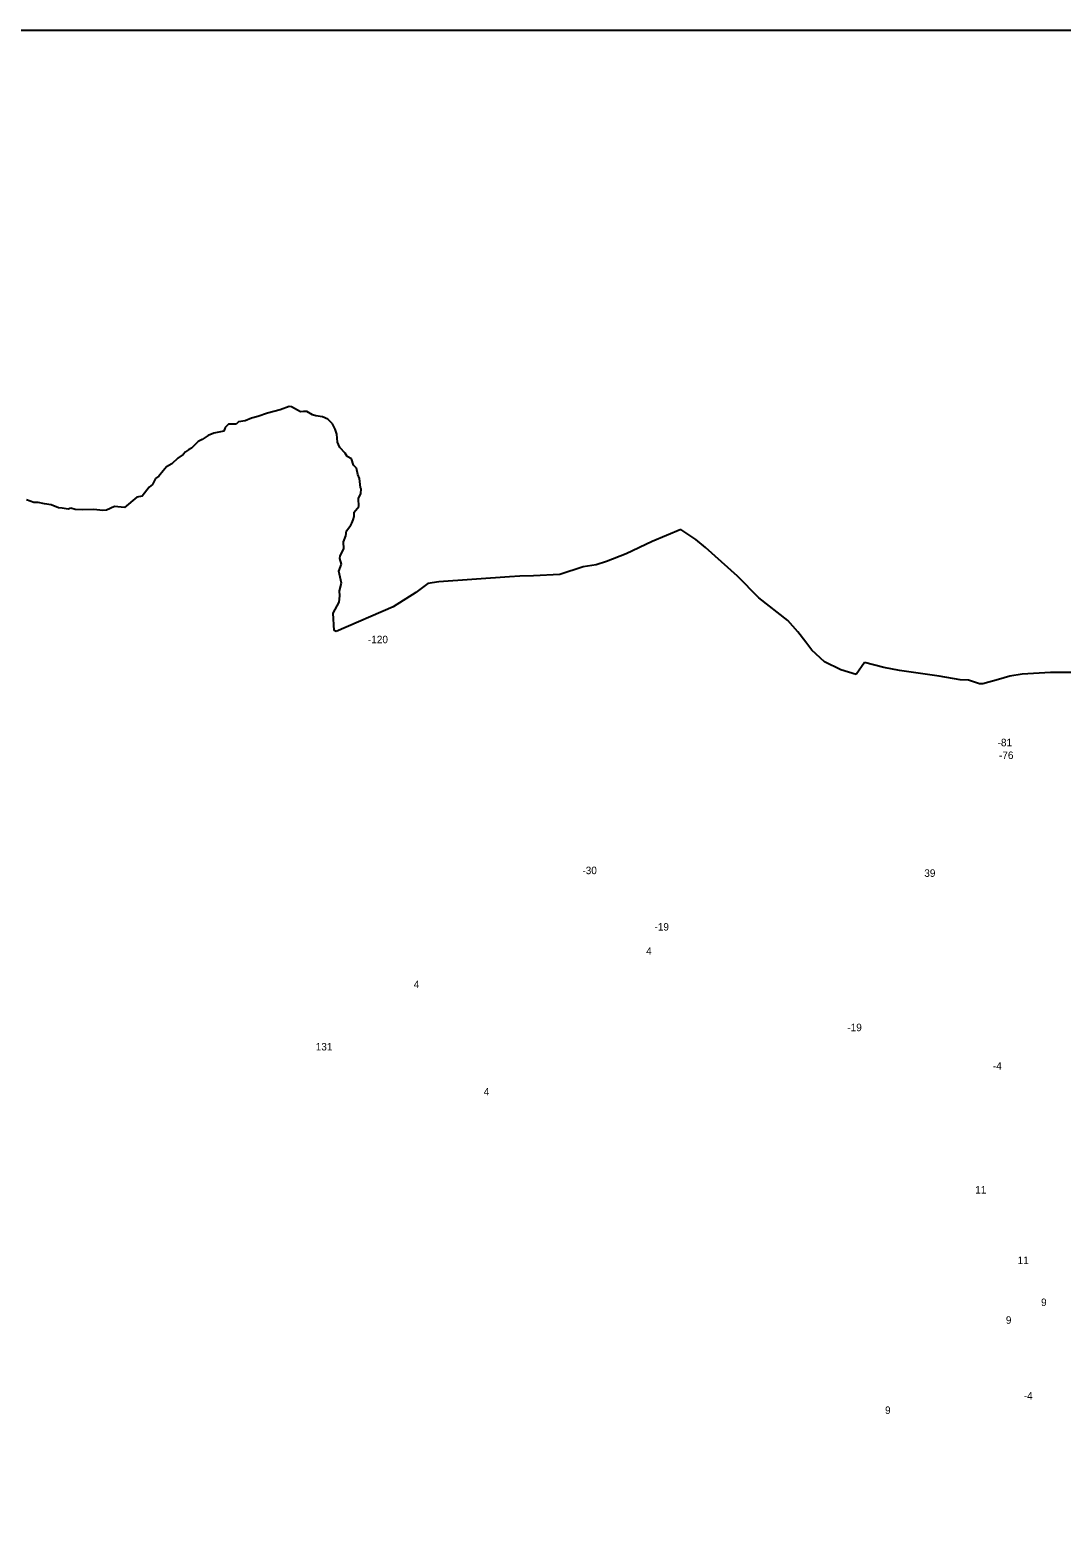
# Model space of a CAD drawing. Extents: x -780246 to -774760, y -968897 to -964868.
# Drawn here: x -777505 to -776126, y -966883 to -964868 of the extents above; entities that cross this region are included whole.
import ezdxf

# ---------------------------------------------------------------- set-up
doc = ezdxf.new("R2010")
doc.units = 0
doc.layers.add('Vrstva 13', color=7, linetype='Continuous')
doc.layers.add('Vrstva 15', color=7, linetype='Continuous')

msp = doc.modelspace()

# ---------------------------------------------------------------- linework, layer by layer
at = {"layer": 'Vrstva 13'}
for p, q in [((-777158.85, -965370.44), (-777170.97, -965374.89)), ((-777155.61, -965370.87), (-777158.85, -965370.44)), ((-777143.79, -965377.55), (-777155.61, -965370.87)), ((-777226.44, -965390.99), (-777229.84, -965393.98)), ((-777217.5, -965389.46), (-777226.44, -965390.99)), ((-777209.29, -965385.95), (-777217.5, -965389.46)), ((-777200.79, -965383.76), (-777209.29, -965385.95)), ((-777187.98, -965379.49), (-777200.79, -965383.76)), ((-777170.97, -965374.89), (-777187.98, -965379.49)), ((-777139.74, -965377.3), (-777143.79, -965377.55)), ((-777135.39, -965377.22), (-777139.74, -965377.3)), ((-777127.54, -965381.64), (-777135.39, -965377.22)), ((-777123.24, -965382.96), (-777127.54, -965381.64)), ((-777114.11, -965384.16), (-777123.24, -965382.96)), ((-777107.07, -965387.45), (-777114.11, -965384.16)), ((-777100.98, -965393.66), (-777107.07, -965387.45)), ((-777267.14, -965409.09), (-777275.06, -965414.5)), ((-777259.65, -965406.24), (-777267.14, -965409.09)), ((-777246.19, -965403.39), (-777259.65, -965406.24)), ((-777244.18, -965398.58), (-777246.19, -965403.39)), ((-777240.05, -965393.94), (-777244.18, -965398.58)), ((-777229.84, -965393.98), (-777240.05, -965393.94)), ((-777097.53, -965400.65), (-777100.98, -965393.66)), ((-777095.25, -965407.28), (-777097.53, -965400.65)), ((-777094.08, -965418.37), (-777095.25, -965407.28)), ((-777297.55, -965431.29), (-777300.32, -965434.5)), ((-777293.6, -965428.4), (-777297.55, -965431.29)), ((-777289.55, -965426.36), (-777293.6, -965428.4)), ((-777280.68, -965417.12), (-777289.55, -965426.36)), ((-777275.06, -965414.5), (-777280.68, -965417.12)), ((-777092.95, -965421.26), (-777094.08, -965418.37)), ((-777091.38, -965425.16), (-777092.95, -965421.26)), ((-777084.15, -965432.9), (-777091.38, -965425.16)), ((-777322.69, -965451.37), (-777327.32, -965456.38)), ((-777315.86, -965446.99), (-777322.69, -965451.37)), ((-777307.8, -965439.54), (-777315.86, -965446.99)), ((-777300.32, -965434.5), (-777307.8, -965439.54)), ((-777081.42, -965437.54), (-777084.15, -965432.9)), ((-777075.51, -965440.57), (-777081.42, -965437.54)), ((-777072.77, -965448.75), (-777075.51, -965440.57)), ((-777068.77, -965453.1), (-777072.77, -965448.75)), ((-777337.32, -965466.71), (-777341.44, -965474.59)), ((-777333.16, -965463.68), (-777337.32, -965466.71)), ((-777327.32, -965456.38), (-777333.16, -965463.68)), ((-777067.07, -965461.24), (-777068.77, -965453.1)), ((-777064.86, -965466.79), (-777067.07, -965461.24)), ((-777063.59, -965478.91), (-777064.86, -965466.79)), ((-777362.6, -965491.61), (-777378.83, -965505.59)), ((-777355.26, -965490.4), (-777362.6, -965491.61)), ((-777345.92, -965478.5), (-777355.26, -965490.4)), ((-777341.44, -965474.59), (-777345.92, -965478.5)), ((-777066.43, -965493.33), (-777062.97, -965487.01)), ((-777062.71, -965480.62), (-777063.59, -965478.91)), ((-777062.97, -965487.01), (-777062.71, -965480.62)), ((-777500.15, -965498.69), (-777509.86, -965495.26)), ((-777494.17, -965498.62), (-777500.15, -965498.69)), ((-777485.97, -965500.63), (-777494.17, -965498.62)), ((-777476.94, -965501.73), (-777485.97, -965500.63)), ((-777467.16, -965506), (-777476.94, -965501.73)), ((-777462.3, -965506.21), (-777467.16, -965506)), ((-777454.31, -965507.53), (-777462.3, -965506.21)), ((-777450.73, -965506.62), (-777454.31, -965507.53)), ((-777444.9, -965508.33), (-777450.73, -965506.62)), ((-777435.62, -965508.51), (-777444.9, -965508.33)), ((-777420.08, -965508.18), (-777435.62, -965508.51)), ((-777407.67, -965509.57), (-777420.08, -965508.18)), ((-777403.14, -965508.95), (-777407.67, -965509.57)), ((-777392.26, -965504.05), (-777403.14, -965508.95)), ((-777378.83, -965505.59), (-777392.26, -965504.05)), ((-777072.05, -965511.95), (-777065.92, -965504.11)), ((-777071.94, -965517.76), (-777072.05, -965511.95)), ((-777065.92, -965504.11), (-777066.43, -965493.33)), ((-777082.3, -965536.74), (-777076.36, -965529)), ((-777076.36, -965529), (-777074.97, -965526.52)), ((-777074.97, -965526.52), (-777073.18, -965521.84)), ((-777073.18, -965521.84), (-777071.94, -965517.76)), ((-777086.14, -965551.4), (-777083, -965543.22)), ((-777085.93, -965560.96), (-777086.14, -965551.4)), ((-777083, -965543.22), (-777082.3, -965536.74)), ((-776673.59, -965551.16), (-776708.69, -965567.66)), ((-776635.58, -965534.96), (-776673.59, -965551.16)), ((-776615.44, -965548.39), (-776635.58, -965534.96)), ((-776602.52, -965558.76), (-776615.44, -965548.39)), ((-777090.98, -965573.7), (-777090.94, -965569.92)), ((-777090.94, -965569.92), (-777085.93, -965560.96)), ((-776708.69, -965567.66), (-776734.59, -965577.88)), ((-776559.84, -965597.37), (-776602.52, -965558.76)), ((-777092.46, -965590.53), (-777089, -965581.07)), ((-777089.11, -965606.62), (-777092.46, -965590.53)), ((-777089, -965581.07), (-777090.98, -965573.7)), ((-776765.89, -965584.82), (-776797.27, -965595.22)), ((-776748.74, -965582.34), (-776765.89, -965584.82)), ((-776734.59, -965577.88), (-776748.74, -965582.34)), ((-777091.81, -965616.69), (-777089.11, -965606.62)), ((-776973.41, -965607.2), (-776989.61, -965619.28)), ((-776958.67, -965604.68), (-776973.41, -965607.2)), ((-776864.55, -965598.15), (-776958.67, -965604.68)), ((-776850.68, -965597.42), (-776864.55, -965598.15)), ((-776832.51, -965596.87), (-776850.68, -965597.42)), ((-776797.27, -965595.22), (-776832.51, -965596.87)), ((-776531.45, -965626.2), (-776559.84, -965597.37)), ((-777100.08, -965646.58), (-777092.2, -965632.13)), ((-777092.2, -965632.13), (-777091, -965623.55)), ((-777091, -965623.55), (-777091.81, -965616.69)), ((-776989.61, -965619.28), (-777019.97, -965638.26)), ((-776492.45, -965656.75), (-776531.45, -965626.2)), ((-777098.62, -965670.09), (-777100.08, -965646.58)), ((-777019.97, -965638.26), (-777095.85, -965671.4)), ((-777095.85, -965671.4), (-777098.62, -965670.09)), ((-776479.28, -965671.5), (-776492.45, -965656.75)), ((-776468.41, -965685.54), (-776479.28, -965671.5)), ((-776460.6, -965696.2), (-776468.41, -965685.54)), ((-776443.38, -965711.89), (-776460.6, -965696.2)), ((-776421.71, -965722.41), (-776443.38, -965711.89)), ((-776389.97, -965712.77), (-776401.35, -965728.83)), ((-776364.07, -965719.49), (-776389.97, -965712.77)), ((-776401.35, -965728.83), (-776421.71, -965722.41)), ((-776343.32, -965723.38), (-776364.07, -965719.49)), ((-776290.15, -965731.07), (-776343.32, -965723.38)), ((-776262.13, -965735.7), (-776290.15, -965731.07)), ((-776195.62, -965731.05), (-776211.09, -965735.36)), ((-776179.13, -965728.14), (-776195.62, -965731.05)), ((-776141.33, -965726.23), (-776179.13, -965728.14)), ((-776111.27, -965726.23), (-776141.33, -965726.23)), ((-776251, -965736.32), (-776262.13, -965735.7)), ((-776236.48, -965741.35), (-776251, -965736.32)), ((-776232.1, -965741.2), (-776236.48, -965741.35)), ((-776211.09, -965735.36), (-776232.1, -965741.2))]:
    msp.add_line(p, q, dxfattribs=at)
msp.add_lwpolyline([(-780246.31, -964867.52), (-774759.73, -964867.52), (-774759.73, -968897.03), (-780246.31, -968897.03)], close=True, dxfattribs=at)

# ---------------------------------------------------------------- texts
at = {"layer": 'Vrstva 15'}
for s, p in [('-120', (-777053.615, -965686.93)), ('-81', (-776212.124, -965824.64)), ('-76', (-776210.282, -965841.65)), ('-30', (-776767.01, -965995.58)), ('39', (-776310.12, -965999.15)), ('-19', (-776670.708, -966071.01)), ('4', (-776681.852, -966103.39)), ('4', (-776992.382, -966147.85)), ('-19', (-776412.948, -966205.43)), ('131', (-777123.366, -966231.18)), ('-4', (-776218.476, -966256.99)), ('4', (-776898.812, -966291.18)), ('11', (-776242.096, -966422.43)), ('11', (-776185.366, -966516.62)), ('9', (-776154.06, -966572.79)), ('9', (-776201.14, -966596.48)), ('-4', (-776177.236, -966697.82)), ('9', (-776362.55, -966717))]:
    msp.add_text(s, height=10, dxfattribs=at).set_placement(p)

doc.saveas('drawing.dxf')
